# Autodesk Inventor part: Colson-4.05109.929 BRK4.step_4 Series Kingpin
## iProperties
Created: 2010-10
Part Number: Colson-4.05109.929 BRK4.step_4 Series Kingpin
Document SubType Name: Modeling
Designer: Administrator
Density: 7.85 g/cm^3
Material: Steel
Mass: 48.1268 g
Surface Area: 23.2631 cm^2
Volume: 6.1308 cm^3
Author: Administrator
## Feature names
1. Base1
